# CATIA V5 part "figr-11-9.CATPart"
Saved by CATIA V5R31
Part number: Part1
Bounding box of the stored display mesh (mm): x -50 to 50, y -39.834 to 41.856, z -25 to 25
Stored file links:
  D:\PROJECTS\Project 2021\US EDITION\CATIA V5 6R 2021\Resources\Part Files\c11_catia_v5_6r2021_prt\figr-11-9.CATPart
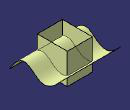
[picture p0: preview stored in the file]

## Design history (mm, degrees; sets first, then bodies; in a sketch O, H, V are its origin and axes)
Set1
  Sketch1 on yz-plane, origin (0, 0, 0), H (0, 1, 0), V (0, 0, 1)
    spline S1 through (-39.8338, -18.0686) (-4.7892, 0) (1.9431, -5.3632) (41.8556, 3.6938)
    point P1 (-4.7892, 0)
    coincidence: P1 H
  Extrude1: Element1 Sketch1, Lim1 50, Lim2 50, Direction yz-plane
  Sketch2 on xy-plane, origin (0, 0, 0), H (1, 0, 0), V (0, 1, 0)
    line L1 (-20.1634, 25.5896) -> (20.7534, 25.5896)
    line L2 (20.7534, 25.5896) -> (20.7534, -23.3463)
    line L3 (20.7534, -23.3463) -> (-20.1634, -23.3463)
    line L4 (-20.1634, -23.3463) -> (-20.1634, 25.5896)
    horizontal: L1 H, L3 H
    vertical: L2 V, L4 V
  Extrude2: Element1 Sketch2, Lim1 25, Lim2 25, Direction xy-plane
  Intersect1: ToIntersect1 Extrude1, ToIntersect2 Extrude2
Body1 (main body)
